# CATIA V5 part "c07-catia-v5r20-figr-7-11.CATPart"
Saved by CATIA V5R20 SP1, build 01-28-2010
Part number: Part1
Bounding box of the stored display mesh (mm): x -50 to 50, y -62.5 to 112.5, z 0 to 100
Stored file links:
  D:\v5_r20\psrt_files_downloaded\c07-catia-v5r20-prt\c07-catia-v5r20-figr-7-11.CATPart
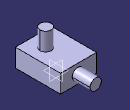
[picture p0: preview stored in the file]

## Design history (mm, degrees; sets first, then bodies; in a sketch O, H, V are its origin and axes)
Body1 (main body)
  Sketch1 on xy-plane, origin (0, 0, 0), H (1, 0, 0), V (0, 1, 0)
    line L1 (-50, 62.5) -> (50, 62.5)
    line L2 (50, 62.5) -> (50, -62.5)
    line L3 (50, -62.5) -> (-50, -62.5)
    line L4 (-50, -62.5) -> (-50, 62.5)
    axis line L5 (50, -62.5) -> (-50, 62.5)
    length L3 = 100
    length L2 = 125
    horizontal: L1 H, L3 H
    vertical: L2 V, L4 V
    midpoint: O L5
  Pad1: profile Sketch1, direction (0, 0, 1), length 50
  Sketch2 on face of Pad1, origin (0, 0, 50), H (1, 0, 0), V (0, 1, 0)
    circle A1 centre (8.7691, -19.7725) radius 15.5717
  Pad2: profile Sketch2, direction (0, 0, 1), length 50
  Sketch3 on face of Pad1, origin (0, 62.5, 112.5), H (1, 0, 0), V (0, 0, -1)
    circle A1 centre (2.1924, 87.7667) radius 15.5717
  Pad3: profile Sketch3, direction (0, 1, 0), length 50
